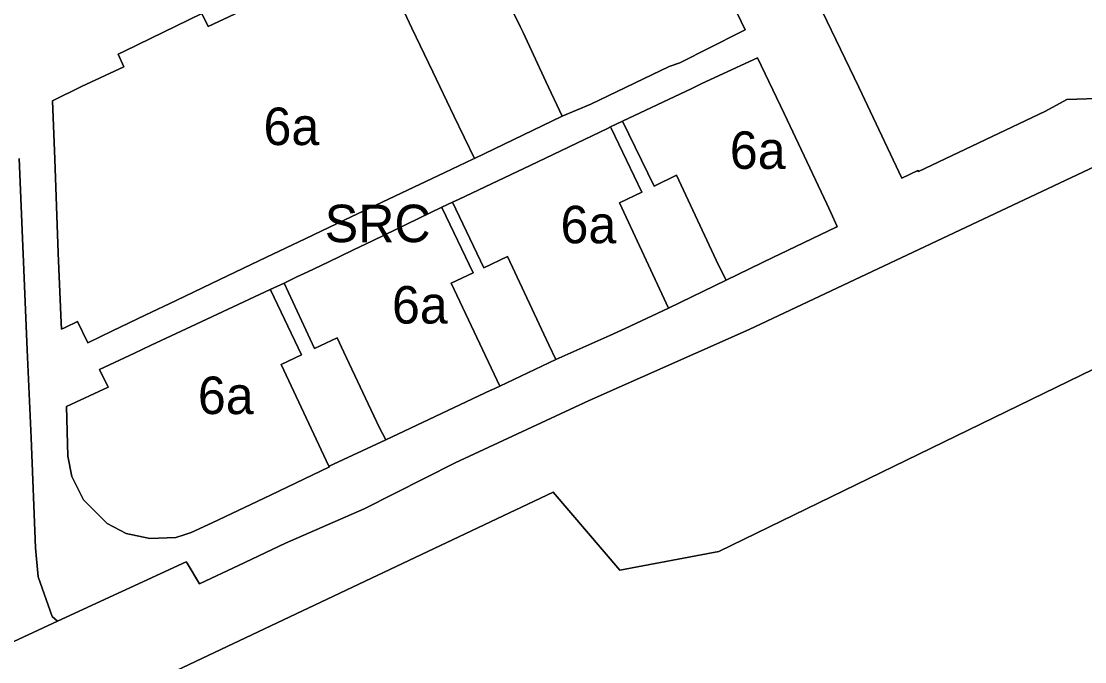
# Model space of a CAD drawing. Extents: x 598968 to 613553, y 4409678 to 4430833.
# Drawn here: x 605740.5 to 606081, y 4415277.9 to 4415482.9 of the extents above; entities that cross this region are included whole.
import ezdxf

# ---------------------------------------------------------------- set-up
doc = ezdxf.new("R2010")
doc.units = 0
for name, color, linetype in [('1', 7, 'Continuous'), ('Polígon industrial de Maó (naus i rafals) - ANNEX III D', 7, 'Continuous'), ('Sòl Rústic Comú', 7, 'Continuous')]:
    doc.layers.add(name, color=color, linetype=linetype)

msp = doc.modelspace()

# ---------------------------------------------------------------- linework, layer by layer
at = {"layer": '1'}
for points in [[(606087.9919, 4415458.3097), (606075.282, 4415457.8795), (606068.5121, 4415454.0694), (606027.8125, 4415434.8089), (606027.6525, 4415435.1489), (606022.5226, 4415432.6989), (606008.6626, 4415461.7583), (605996.9526, 4415486.1579), (605993.0526, 4415494.8377), (605985.5526, 4415510.7874), (605978.0126, 4415526.5371), (605970.5827, 4415542.0668), (605963.0927, 4415558.3665), (606007.8101, 4415579.7366), (606017.2321, 4415584.4972), (606024.9753, 4415568.0868), (606039.7421, 4415535.9781), (606048.692, 4415540.6882), (606025.892, 4415588.5273), (606030.6063, 4415590.8951), (606029.0434, 4415594.007), (606071.9315, 4415615.5478), (606079.2414, 4415619.4279), (606118.6109, 4415637.4883)], [(605739.8262, 4415439.0203), (605742.4364, 4415377.6909), (605743.7265, 4415349.6112), (605745.0766, 4415314.3816), (605745.9766, 4415305.0517), (605750.4866, 4415292.4319), (605752.1398, 4415290.8862), (605793.3719, 4415309.9219), (605793.6554, 4415309.4444), (605797.5694, 4415302.8522), (605797.8641, 4415302.9909), (605810.0857, 4415308.7421), (605825.1238, 4415315.8187), (605850.355, 4415326.8812), (605879.4637, 4415341.5373), (605922.3502, 4415361.5323), (605973.5659, 4415384.2565), (606444.3643, 4415606.2638)], [(605959.3829, 4415507.157), (605972.3629, 4415480.1075), (605971.5013, 4415479.6939), (605970.856, 4415479.3841), (605951.4331, 4415469.5973), (605947.9731, 4415468.3972), (605922.9034, 4415456.3669), (605913.6835, 4415452.4668), (605885.6225, 4415438.9633), (605885.118, 4415438.7279), (605876.1092, 4415434.525), (605844.1645, 4415419.3723), (605831.4662, 4415413.2213), (605819.0945, 4415407.3857), (605804.1119, 4415400.2983), (605790.1467, 4415393.5293), (605780.2245, 4415388.8041), (605769.7332, 4415383.8078), (605761.8051, 4415380.025), (605758.5552, 4415386.8249), (605754.5452, 4415384.9248), (605753.4334, 4415384.3981), (605753.3452, 4415386.3348), (605752.3251, 4415408.7145), (605751.2587, 4415438.8027), (605750.575, 4415457.454), (605759.8449, 4415461.9641), (605773.3548, 4415468.3442), (605771.5748, 4415472.3442), (605773.572, 4415473.3174), (605798.3144, 4415485.3745), (605800.4344, 4415481.1646), (605813.8443, 4415487.5047)], [(605722.6392, 4415277.2668), (605752.1398, 4415290.8862), (605750.4866, 4415292.4319), (605745.9766, 4415305.0517), (605745.0766, 4415314.3816), (605743.7265, 4415349.6112), (605742.4364, 4415377.6909), (605739.8262, 4415439.0203)]]:
    msp.add_lwpolyline(points, dxfattribs=at)
for points in [[(605913.6835, 4415452.4668), (605908.4923, 4415463.6371), (605901.2199, 4415479.2857), (605900.385, 4415480.9995), (605900.3835, 4415481.0026), (605894.6035, 4415492.866), (605881.7135, 4415519.8956), (605853.5355, 4415506.1681), (605858.9213, 4415494.7839), (605862.4239, 4415487.4616), (605865.6437, 4415480.7305), (605872.3563, 4415466.6972), (605879.0729, 4415452.6558), (605885.6225, 4415438.9633)], [(605933.0249, 4415450.8838), (605955.2327, 4415461.3986), (605956.0981, 4415461.8082), (605958.463, 4415462.9274), (605976.2329, 4415471.2377), (605984.8328, 4415453.328), (605998.4868, 4415424.4273), (605999.7828, 4415421.6886), (606001.8028, 4415417.2087), (606001.4552, 4415417.0422), (605983.4222, 4415408.3737), (605981.4166, 4415407.4046), (605966.2332, 4415400.0683), (605947.7534, 4415391.068), (605933.9035, 4415384.5879), (605928.9436, 4415382.3578), (605911.7138, 4415374.6276), (605893.7225, 4415366.1591), (605890.9512, 4415364.8091), (605890.9278, 4415364.7982), (605857.3143, 4415348.9169), (605839.0719, 4415340.5506), (605839.2056, 4415340.2667), (605820.3699, 4415331.2785), (605801.6899, 4415322.4239), (605794.965, 4415319.2362), (605792.6791, 4415318.5612), (605790.0613, 4415317.7287), (605781.7417, 4415317.3128), (605774.15, 4415318.9954), (605768.091, 4415322.1764), (605760.4397, 4415329.762), (605756.6976, 4415337.1726), (605755.4953, 4415343.6852), (605754.9853, 4415359.5651), (605768.3151, 4415365.8052), (605765.6251, 4415371.4451), (605776.7677, 4415376.6858), (605782.1643, 4415379.2347), (605794.9122, 4415385.2559), (605820.2749, 4415397.0534), (605824.7503, 4415399.1106), (605828.8044, 4415401.0659), (605832.3144, 4415402.716), (605838.7993, 4415405.821), (605846.9092, 4415409.7011), (605852.9942, 4415412.6462), (605875.1539, 4415423.3865), (605878.6439, 4415424.9965), (605880.7348, 4415425.9613), (605903.5273, 4415436.7567), (605928.286, 4415448.6027), (605929.2469, 4415449.066)], [(605966.2332, 4415400.0683), (605963.8232, 4415404.8682), (605950.3632, 4415433.5976), (605943.1651, 4415430.0742), (605933.0249, 4415450.8838), (605929.2469, 4415449.066), (605929.3679, 4415448.6647), (605939.236, 4415428.1977), (605932.0478, 4415424.7646), (605947.7534, 4415391.068)], [(605911.7138, 4415374.6276), (605909.4538, 4415379.3575), (605896.1863, 4415407.6373), (605888.5934, 4415404.011), (605878.6439, 4415424.9965), (605875.1539, 4415423.3865), (605875.321, 4415423.0378), (605885.2139, 4415402.3969), (605885.1901, 4415402.3859), (605878.134, 4415399.1268), (605893.7225, 4415366.1591)], [(605857.3143, 4415348.9169), (605855.1743, 4415352.9469), (605843.8276, 4415376.9517), (605841.6344, 4415381.5763), (605834.4744, 4415378.1462), (605824.7503, 4415399.1106), (605820.2749, 4415397.0534), (605820.4376, 4415396.7055), (605830.2701, 4415376.1464), (605823.7746, 4415373.0161), (605839.0159, 4415340.5249), (605839.0719, 4415340.5506)]]:
    msp.add_lwpolyline(points, close=True, dxfattribs=at)
at = {"layer": 'Polígon industrial de Maó (naus i rafals) - ANNEX III D'}
for points in [[(606118.6109, 4415637.4883), (606079.2414, 4415619.4279), (606071.9315, 4415615.5478), (606029.0434, 4415594.007), (606030.6063, 4415590.8951), (606025.892, 4415588.5273), (606048.692, 4415540.6882), (606039.7421, 4415535.9781), (606024.9753, 4415568.0868), (606017.2321, 4415584.4972), (606007.8101, 4415579.7366), (605963.0927, 4415558.3665), (605970.5827, 4415542.0668), (605978.0126, 4415526.5371), (605985.5526, 4415510.7874), (605993.0526, 4415494.8377), (605996.9526, 4415486.1579), (606008.6626, 4415461.7583), (606022.5226, 4415432.6989), (606027.6525, 4415435.1489), (606027.8125, 4415434.8089), (606068.5121, 4415454.0694), (606075.282, 4415457.8795), (606087.9919, 4415458.3097)], [(605813.8443, 4415487.5047), (605800.4344, 4415481.1646), (605798.3144, 4415485.3745), (605773.572, 4415473.3174), (605771.5748, 4415472.3442), (605773.3548, 4415468.3442), (605759.8449, 4415461.9641), (605750.575, 4415457.454), (605751.2587, 4415438.8027), (605752.3251, 4415408.7145), (605753.3452, 4415386.3348), (605753.4334, 4415384.3981), (605754.5452, 4415384.9248), (605758.5552, 4415386.8249), (605761.8051, 4415380.025), (605769.7332, 4415383.8078), (605780.2245, 4415388.8041), (605790.1467, 4415393.5293), (605804.1119, 4415400.2983), (605819.0945, 4415407.3857), (605831.4662, 4415413.2213), (605844.1645, 4415419.3723), (605876.1092, 4415434.525), (605885.118, 4415438.7279), (605885.6225, 4415438.9633), (605879.0729, 4415452.6558), (605872.3563, 4415466.6972), (605865.6437, 4415480.7305), (605862.4239, 4415487.4616)]]:
    msp.add_lwpolyline(points, dxfattribs=at)
for points in [[(605913.6835, 4415452.4668), (605922.9034, 4415456.3669), (605947.9731, 4415468.3972), (605951.4331, 4415469.5973), (605970.856, 4415479.3841), (605971.5013, 4415479.6939), (605972.3629, 4415480.1075), (605959.3829, 4415507.157), (605953.1129, 4415521.0668), (605945.3167, 4415537.2765), (605940.2087, 4415547.8943), (605926.0951, 4415541.1092), (605890.9634, 4415524.2157), (605881.7135, 4415519.8956), (605894.6035, 4415492.866), (605900.3835, 4415481.0026), (605900.385, 4415480.9995), (605901.2199, 4415479.2857), (605908.4923, 4415463.6371)], [(605966.2332, 4415400.0683), (605981.4166, 4415407.4046), (605983.4222, 4415408.3737), (606001.4552, 4415417.0422), (606001.8028, 4415417.2087), (605999.7828, 4415421.6886), (605998.4868, 4415424.4273), (605984.8328, 4415453.328), (605976.2329, 4415471.2377), (605958.463, 4415462.9274), (605956.0981, 4415461.8082), (605955.2327, 4415461.3986), (605933.0249, 4415450.8838), (605943.1651, 4415430.0742), (605950.3632, 4415433.5976), (605963.8232, 4415404.8682)], [(605947.7534, 4415391.068), (605932.0478, 4415424.7646), (605939.236, 4415428.1977), (605929.3679, 4415448.6647), (605929.2469, 4415449.066), (605928.286, 4415448.6027), (605903.5273, 4415436.7567), (605880.7348, 4415425.9613), (605878.6439, 4415424.9965), (605888.5934, 4415404.011), (605896.1863, 4415407.6373), (605909.4538, 4415379.3575), (605911.7138, 4415374.6276), (605928.9436, 4415382.3578), (605933.9035, 4415384.5879)], [(605893.7225, 4415366.1591), (605878.134, 4415399.1268), (605885.1901, 4415402.3859), (605885.2139, 4415402.3969), (605875.321, 4415423.0378), (605875.1539, 4415423.3865), (605852.9942, 4415412.6462), (605846.9092, 4415409.7011), (605838.7993, 4415405.821), (605832.3144, 4415402.716), (605828.8044, 4415401.0659), (605824.7503, 4415399.1106), (605834.4744, 4415378.1462), (605841.6344, 4415381.5763), (605843.8276, 4415376.9517), (605855.1743, 4415352.9469), (605857.3143, 4415348.9169), (605890.9278, 4415364.7982), (605890.9512, 4415364.8091)], [(605839.0719, 4415340.5506), (605839.0159, 4415340.5249), (605823.7746, 4415373.0161), (605830.2701, 4415376.1464), (605820.4376, 4415396.7055), (605820.2749, 4415397.0534), (605794.9122, 4415385.2559), (605782.1643, 4415379.2347), (605776.7677, 4415376.6858), (605765.6251, 4415371.4451), (605768.3151, 4415365.8052), (605754.9853, 4415359.5651), (605755.4953, 4415343.6852), (605756.6976, 4415337.1726), (605760.4397, 4415329.762), (605768.091, 4415322.1764), (605774.15, 4415318.9954), (605781.7417, 4415317.3128), (605790.0613, 4415317.7287), (605792.6791, 4415318.5612), (605794.965, 4415319.2362), (605801.6899, 4415322.4239), (605820.3699, 4415331.2785), (605839.2056, 4415340.2667)]]:
    msp.add_lwpolyline(points, close=True, dxfattribs=at)
at = {"layer": 'Sòl Rústic Comú'}
for points in [[(606748.099, 4415756.8444), (606523.4548, 4415650.3535), (606526.3041, 4415644.9028), (606444.3643, 4415606.2638), (605973.5659, 4415384.2565), (605922.3502, 4415361.5323), (605879.4637, 4415341.5373), (605850.355, 4415326.8812), (605825.1238, 4415315.8187), (605810.0857, 4415308.7421), (605797.8641, 4415302.9909), (605797.5694, 4415302.8522), (605793.6554, 4415309.4444), (605793.3719, 4415309.9219), (605752.1398, 4415290.8862), (605722.6392, 4415277.2668)], [(605729.9823, 4415246.6932), (605910.7971, 4415332.1936), (605932.1721, 4415307.1936), (605963.9225, 4415313.1936), (606487.8665, 4415568.1946), (606524.1169, 4415574.1946), (606607.1803, 4415615.6948), (606612.0555, 4415639.6948), (606636.9933, 4415649.6948), (606654.3683, 4415617.1948)], [(606654.3683, 4415617.1948), (606636.9933, 4415649.6948), (606612.0555, 4415639.6948), (606607.1803, 4415615.6948), (606524.1169, 4415574.1946), (606487.8665, 4415568.1946), (605963.9225, 4415313.1936), (605932.1721, 4415307.1936), (605910.7971, 4415332.1936), (605729.9823, 4415246.6932)]]:
    msp.add_lwpolyline(points, dxfattribs=at)

# ---------------------------------------------------------------- texts
at = {"layer": 'Polígon industrial de Maó (naus i rafals) - ANNEX III D'}
for p in [(605818.0987, 4415443.2708), (605967.4138, 4415435.653), (605913.1986, 4415411.8468), (605859.2364, 4415386.1517), (605797.0954, 4415357.1831)]:
    msp.add_text('6a', height=12, dxfattribs=at).set_placement(p)
at = {"layer": 'Sòl Rústic Comú'}
msp.add_text('SRC', height=12, dxfattribs=at).set_placement((605837.7077, 4415412.1925))

doc.saveas('drawing.dxf')
